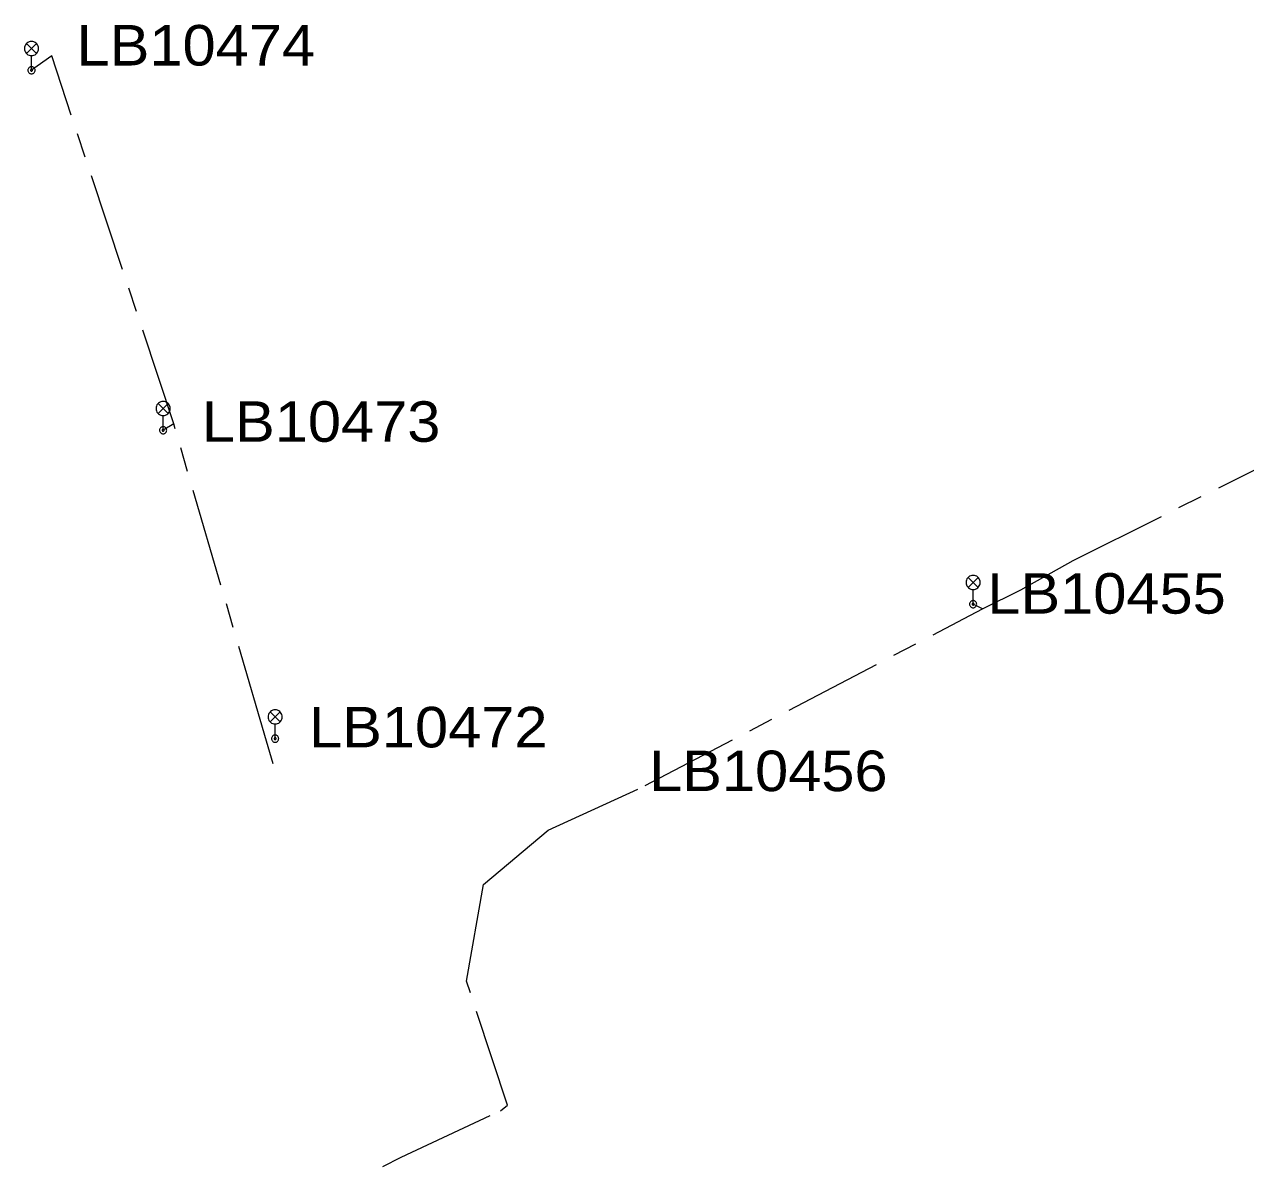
# Model space of a CAD drawing. Extents: x -691843 to -691118, y -976392 to -975793.
# Drawn here: x -691843.2 to -691778.5, y -976381.8 to -976321.3 of the extents above; entities that cross this region are included whole.
import ezdxf

# ---------------------------------------------------------------- set-up
doc = ezdxf.new("R2010")
doc.units = 0
doc.header["$LTSCALE"] = 0.87
doc.linetypes.add('LONG_DASH_SHORT_DASH', pattern=[9.9, 6, -1.2, 1.5, -1.2])
doc.layers.add('1', color=7, linetype='Continuous', lineweight=13)

msp = doc.modelspace()

# ---------------------------------------------------------------- linework, layer by layer
at = {"layer": '1'}
for p, q in [((-691843.095, -976322.285), (-691842.565, -976322.815)), ((-691843.095, -976322.815), (-691842.565, -976322.285)), ((-691842.83, -976323.7), (-691842.83, -976322.925)), ((-691836.125, -976341.345), (-691835.595, -976341.875)), ((-691836.125, -976341.875), (-691835.595, -976341.345)), ((-691835.86, -976342.76), (-691835.86, -976341.985)), ((-691793.235, -976350.555), (-691792.705, -976351.085)), ((-691793.235, -976351.085), (-691792.705, -976350.555)), ((-691792.97, -976351.97), (-691792.97, -976351.195)), ((-691830.195, -976357.675), (-691829.665, -976358.205)), ((-691830.195, -976358.205), (-691829.665, -976357.675)), ((-691829.93, -976359.09), (-691829.93, -976358.315))]:
    msp.add_line(p, q, dxfattribs=at)
at = {"layer": '1', "linetype": 'LONG_DASH_SHORT_DASH'}
for p, q in [((-691841.76, -976322.94), (-691842.83, -976323.7)), ((-691841.76, -976322.94), (-691842.83, -976323.7)), ((-691841.76, -976322.94), (-691842.83, -976323.7)), ((-691841.76, -976322.94), (-691842.83, -976323.7)), ((-691841.76, -976322.94), (-691842.83, -976323.7)), ((-691841.76, -976322.94), (-691842.83, -976323.7)), ((-691841.76, -976322.94), (-691842.83, -976323.7)), ((-691841.76, -976322.94), (-691842.83, -976323.7)), ((-691835.3, -976342.42), (-691835.86, -976342.76)), ((-691835.3, -976342.42), (-691835.86, -976342.76)), ((-691835.3, -976342.42), (-691835.86, -976342.76)), ((-691835.3, -976342.42), (-691835.86, -976342.76)), ((-691835.3, -976342.42), (-691835.86, -976342.76)), ((-691835.3, -976342.42), (-691835.86, -976342.76)), ((-691835.3, -976342.42), (-691835.86, -976342.76)), ((-691835.3, -976342.42), (-691835.86, -976342.76)), ((-691790.45, -976351.22), (-691787.67, -976349.66)), ((-691790.45, -976351.22), (-691787.67, -976349.66)), ((-691790.45, -976351.22), (-691787.67, -976349.66)), ((-691790.45, -976351.22), (-691787.67, -976349.66)), ((-691790.45, -976351.22), (-691787.67, -976349.66)), ((-691790.45, -976351.22), (-691787.67, -976349.66)), ((-691790.45, -976351.22), (-691787.67, -976349.66)), ((-691792.47, -976352.22), (-691792.97, -976351.97)), ((-691792.47, -976352.22), (-691792.97, -976351.97)), ((-691792.47, -976352.22), (-691792.97, -976351.97)), ((-691792.47, -976352.22), (-691792.97, -976351.97)), ((-691792.47, -976352.22), (-691792.97, -976351.97)), ((-691792.47, -976352.22), (-691792.97, -976351.97)), ((-691792.47, -976352.22), (-691792.97, -976351.97)), ((-691792.47, -976352.22), (-691792.97, -976351.97))]:
    msp.add_line(p, q, dxfattribs=at)
at = {"layer": '1'}
for points in [[(-691842.455, -976322.55), (-691842.461, -976322.485), (-691842.478, -976322.422), (-691842.505, -976322.362), (-691842.543, -976322.309), (-691842.589, -976322.263), (-691842.642, -976322.225), (-691842.702, -976322.198), (-691842.765, -976322.181), (-691842.83, -976322.175), (-691842.895, -976322.181), (-691842.958, -976322.198), (-691843.018, -976322.225), (-691843.071, -976322.263), (-691843.117, -976322.309), (-691843.155, -976322.362), (-691843.182, -976322.422), (-691843.199, -976322.485), (-691843.205, -976322.55), (-691843.199, -976322.615), (-691843.182, -976322.678), (-691843.155, -976322.737), (-691843.117, -976322.791), (-691843.071, -976322.837), (-691843.018, -976322.875), (-691842.958, -976322.902), (-691842.895, -976322.919), (-691842.83, -976322.925), (-691842.765, -976322.919), (-691842.702, -976322.902), (-691842.642, -976322.875), (-691842.589, -976322.837), (-691842.543, -976322.791), (-691842.505, -976322.737), (-691842.478, -976322.678), (-691842.461, -976322.615)], [(-691842.64, -976323.7), (-691842.643, -976323.667), (-691842.651, -976323.635), (-691842.665, -976323.605), (-691842.684, -976323.578), (-691842.708, -976323.554), (-691842.735, -976323.535), (-691842.765, -976323.521), (-691842.797, -976323.513), (-691842.83, -976323.51), (-691842.863, -976323.513), (-691842.895, -976323.521), (-691842.925, -976323.535), (-691842.952, -976323.554), (-691842.976, -976323.578), (-691842.995, -976323.605), (-691843.009, -976323.635), (-691843.017, -976323.667), (-691843.02, -976323.7), (-691843.017, -976323.733), (-691843.009, -976323.765), (-691842.995, -976323.795), (-691842.976, -976323.822), (-691842.952, -976323.846), (-691842.925, -976323.865), (-691842.895, -976323.879), (-691842.863, -976323.887), (-691842.83, -976323.89), (-691842.797, -976323.887), (-691842.765, -976323.879), (-691842.735, -976323.865), (-691842.708, -976323.846), (-691842.684, -976323.822), (-691842.665, -976323.795), (-691842.651, -976323.765), (-691842.643, -976323.733)], [(-691842.78, -976323.7), (-691842.781, -976323.691), (-691842.783, -976323.683), (-691842.787, -976323.675), (-691842.792, -976323.668), (-691842.798, -976323.662), (-691842.805, -976323.657), (-691842.813, -976323.653), (-691842.821, -976323.651), (-691842.83, -976323.65), (-691842.839, -976323.651), (-691842.847, -976323.653), (-691842.855, -976323.657), (-691842.862, -976323.662), (-691842.868, -976323.668), (-691842.873, -976323.675), (-691842.877, -976323.683), (-691842.879, -976323.691), (-691842.88, -976323.7), (-691842.879, -976323.709), (-691842.877, -976323.717), (-691842.873, -976323.725), (-691842.868, -976323.732), (-691842.862, -976323.738), (-691842.855, -976323.743), (-691842.847, -976323.747), (-691842.839, -976323.749), (-691842.83, -976323.75), (-691842.821, -976323.749), (-691842.813, -976323.747), (-691842.805, -976323.743), (-691842.798, -976323.738), (-691842.792, -976323.732), (-691842.787, -976323.725), (-691842.783, -976323.717), (-691842.781, -976323.709)], [(-691835.485, -976341.61), (-691835.491, -976341.545), (-691835.508, -976341.482), (-691835.535, -976341.423), (-691835.573, -976341.369), (-691835.619, -976341.323), (-691835.672, -976341.285), (-691835.732, -976341.258), (-691835.795, -976341.241), (-691835.86, -976341.235), (-691835.925, -976341.241), (-691835.988, -976341.258), (-691836.048, -976341.285), (-691836.101, -976341.323), (-691836.147, -976341.369), (-691836.185, -976341.423), (-691836.212, -976341.482), (-691836.229, -976341.545), (-691836.235, -976341.61), (-691836.229, -976341.675), (-691836.212, -976341.738), (-691836.185, -976341.798), (-691836.147, -976341.851), (-691836.101, -976341.897), (-691836.048, -976341.935), (-691835.988, -976341.962), (-691835.925, -976341.979), (-691835.86, -976341.985), (-691835.795, -976341.979), (-691835.732, -976341.962), (-691835.672, -976341.935), (-691835.619, -976341.897), (-691835.573, -976341.851), (-691835.535, -976341.798), (-691835.508, -976341.738), (-691835.491, -976341.675)], [(-691835.67, -976342.76), (-691835.673, -976342.727), (-691835.681, -976342.695), (-691835.695, -976342.665), (-691835.714, -976342.638), (-691835.738, -976342.614), (-691835.765, -976342.595), (-691835.795, -976342.581), (-691835.827, -976342.573), (-691835.86, -976342.57), (-691835.893, -976342.573), (-691835.925, -976342.581), (-691835.955, -976342.595), (-691835.982, -976342.614), (-691836.006, -976342.638), (-691836.025, -976342.665), (-691836.039, -976342.695), (-691836.047, -976342.727), (-691836.05, -976342.76), (-691836.047, -976342.793), (-691836.039, -976342.825), (-691836.025, -976342.855), (-691836.006, -976342.882), (-691835.982, -976342.906), (-691835.955, -976342.925), (-691835.925, -976342.939), (-691835.893, -976342.947), (-691835.86, -976342.95), (-691835.827, -976342.947), (-691835.795, -976342.939), (-691835.765, -976342.925), (-691835.738, -976342.906), (-691835.714, -976342.882), (-691835.695, -976342.855), (-691835.681, -976342.825), (-691835.673, -976342.793)], [(-691835.81, -976342.76), (-691835.811, -976342.751), (-691835.813, -976342.743), (-691835.817, -976342.735), (-691835.822, -976342.728), (-691835.828, -976342.722), (-691835.835, -976342.717), (-691835.843, -976342.713), (-691835.851, -976342.711), (-691835.86, -976342.71), (-691835.869, -976342.711), (-691835.877, -976342.713), (-691835.885, -976342.717), (-691835.892, -976342.722), (-691835.898, -976342.728), (-691835.903, -976342.735), (-691835.907, -976342.743), (-691835.909, -976342.751), (-691835.91, -976342.76), (-691835.909, -976342.769), (-691835.907, -976342.777), (-691835.903, -976342.785), (-691835.898, -976342.792), (-691835.892, -976342.798), (-691835.885, -976342.803), (-691835.877, -976342.807), (-691835.869, -976342.809), (-691835.86, -976342.81), (-691835.851, -976342.809), (-691835.843, -976342.807), (-691835.835, -976342.803), (-691835.828, -976342.798), (-691835.822, -976342.792), (-691835.817, -976342.785), (-691835.813, -976342.777), (-691835.811, -976342.769)], [(-691792.595, -976350.82), (-691792.601, -976350.755), (-691792.618, -976350.692), (-691792.645, -976350.633), (-691792.683, -976350.579), (-691792.729, -976350.533), (-691792.782, -976350.495), (-691792.842, -976350.468), (-691792.905, -976350.451), (-691792.97, -976350.445), (-691793.035, -976350.451), (-691793.098, -976350.468), (-691793.158, -976350.495), (-691793.211, -976350.533), (-691793.257, -976350.579), (-691793.295, -976350.633), (-691793.322, -976350.692), (-691793.339, -976350.755), (-691793.345, -976350.82), (-691793.339, -976350.885), (-691793.322, -976350.948), (-691793.295, -976351.008), (-691793.257, -976351.061), (-691793.211, -976351.107), (-691793.158, -976351.145), (-691793.098, -976351.172), (-691793.035, -976351.189), (-691792.97, -976351.195), (-691792.905, -976351.189), (-691792.842, -976351.172), (-691792.782, -976351.145), (-691792.729, -976351.107), (-691792.683, -976351.061), (-691792.645, -976351.008), (-691792.618, -976350.948), (-691792.601, -976350.885)], [(-691792.78, -976351.97), (-691792.783, -976351.937), (-691792.791, -976351.905), (-691792.805, -976351.875), (-691792.824, -976351.848), (-691792.848, -976351.824), (-691792.875, -976351.805), (-691792.905, -976351.791), (-691792.937, -976351.783), (-691792.97, -976351.78), (-691793.003, -976351.783), (-691793.035, -976351.791), (-691793.065, -976351.805), (-691793.092, -976351.824), (-691793.116, -976351.848), (-691793.135, -976351.875), (-691793.149, -976351.905), (-691793.157, -976351.937), (-691793.16, -976351.97), (-691793.157, -976352.003), (-691793.149, -976352.035), (-691793.135, -976352.065), (-691793.116, -976352.092), (-691793.092, -976352.116), (-691793.065, -976352.135), (-691793.035, -976352.149), (-691793.003, -976352.157), (-691792.97, -976352.16), (-691792.937, -976352.157), (-691792.905, -976352.149), (-691792.875, -976352.135), (-691792.848, -976352.116), (-691792.824, -976352.092), (-691792.805, -976352.065), (-691792.791, -976352.035), (-691792.783, -976352.003)], [(-691792.92, -976351.97), (-691792.921, -976351.961), (-691792.923, -976351.953), (-691792.927, -976351.945), (-691792.932, -976351.938), (-691792.938, -976351.932), (-691792.945, -976351.927), (-691792.953, -976351.923), (-691792.961, -976351.921), (-691792.97, -976351.92), (-691792.979, -976351.921), (-691792.987, -976351.923), (-691792.995, -976351.927), (-691793.002, -976351.932), (-691793.008, -976351.938), (-691793.013, -976351.945), (-691793.017, -976351.953), (-691793.019, -976351.961), (-691793.02, -976351.97), (-691793.019, -976351.979), (-691793.017, -976351.987), (-691793.013, -976351.995), (-691793.008, -976352.002), (-691793.002, -976352.008), (-691792.995, -976352.013), (-691792.987, -976352.017), (-691792.979, -976352.019), (-691792.97, -976352.02), (-691792.961, -976352.019), (-691792.953, -976352.017), (-691792.945, -976352.013), (-691792.938, -976352.008), (-691792.932, -976352.002), (-691792.927, -976351.995), (-691792.923, -976351.987), (-691792.921, -976351.979)], [(-691829.555, -976357.94), (-691829.561, -976357.875), (-691829.578, -976357.812), (-691829.605, -976357.753), (-691829.643, -976357.699), (-691829.689, -976357.653), (-691829.742, -976357.615), (-691829.802, -976357.588), (-691829.865, -976357.571), (-691829.93, -976357.565), (-691829.995, -976357.571), (-691830.058, -976357.588), (-691830.118, -976357.615), (-691830.171, -976357.653), (-691830.217, -976357.699), (-691830.255, -976357.753), (-691830.282, -976357.812), (-691830.299, -976357.875), (-691830.305, -976357.94), (-691830.299, -976358.005), (-691830.282, -976358.068), (-691830.255, -976358.128), (-691830.217, -976358.181), (-691830.171, -976358.227), (-691830.118, -976358.265), (-691830.058, -976358.292), (-691829.995, -976358.309), (-691829.93, -976358.315), (-691829.865, -976358.309), (-691829.802, -976358.292), (-691829.742, -976358.265), (-691829.689, -976358.227), (-691829.643, -976358.181), (-691829.605, -976358.128), (-691829.578, -976358.068), (-691829.561, -976358.005)], [(-691829.74, -976359.09), (-691829.743, -976359.057), (-691829.751, -976359.025), (-691829.765, -976358.995), (-691829.784, -976358.968), (-691829.808, -976358.944), (-691829.835, -976358.925), (-691829.865, -976358.911), (-691829.897, -976358.903), (-691829.93, -976358.9), (-691829.963, -976358.903), (-691829.995, -976358.911), (-691830.025, -976358.925), (-691830.052, -976358.944), (-691830.076, -976358.968), (-691830.095, -976358.995), (-691830.109, -976359.025), (-691830.117, -976359.057), (-691830.12, -976359.09), (-691830.117, -976359.123), (-691830.109, -976359.155), (-691830.095, -976359.185), (-691830.076, -976359.212), (-691830.052, -976359.236), (-691830.025, -976359.255), (-691829.995, -976359.269), (-691829.963, -976359.277), (-691829.93, -976359.28), (-691829.897, -976359.277), (-691829.865, -976359.269), (-691829.835, -976359.255), (-691829.808, -976359.236), (-691829.784, -976359.212), (-691829.765, -976359.185), (-691829.751, -976359.155), (-691829.743, -976359.123)], [(-691829.88, -976359.09), (-691829.881, -976359.081), (-691829.883, -976359.073), (-691829.887, -976359.065), (-691829.892, -976359.058), (-691829.898, -976359.052), (-691829.905, -976359.047), (-691829.913, -976359.043), (-691829.921, -976359.041), (-691829.93, -976359.04), (-691829.939, -976359.041), (-691829.947, -976359.043), (-691829.955, -976359.047), (-691829.962, -976359.052), (-691829.968, -976359.058), (-691829.973, -976359.065), (-691829.977, -976359.073), (-691829.979, -976359.081), (-691829.98, -976359.09), (-691829.979, -976359.099), (-691829.977, -976359.107), (-691829.973, -976359.115), (-691829.968, -976359.122), (-691829.962, -976359.128), (-691829.955, -976359.133), (-691829.947, -976359.137), (-691829.939, -976359.139), (-691829.93, -976359.14), (-691829.921, -976359.139), (-691829.913, -976359.137), (-691829.905, -976359.133), (-691829.898, -976359.128), (-691829.892, -976359.122), (-691829.887, -976359.115), (-691829.883, -976359.107), (-691829.881, -976359.099)]]:
    msp.add_lwpolyline(points, close=True, dxfattribs=at)
at = {"layer": '1', "linetype": 'LONG_DASH_SHORT_DASH'}
for points in [[(-691830.04, -976360.42), (-691830.389, -976359.224), (-691835.3, -976342.42), (-691841.76, -976322.94)], [(-691830.04, -976360.42), (-691830.389, -976359.224), (-691835.3, -976342.42), (-691841.76, -976322.94)], [(-691830.04, -976360.42), (-691830.389, -976359.224), (-691835.3, -976342.42), (-691841.76, -976322.94)], [(-691830.04, -976360.42), (-691830.389, -976359.224), (-691835.3, -976342.42), (-691841.76, -976322.94)], [(-691830.04, -976360.42), (-691830.389, -976359.224), (-691835.3, -976342.42), (-691841.76, -976322.94)], [(-691830.04, -976360.42), (-691830.389, -976359.224), (-691835.3, -976342.42), (-691841.76, -976322.94)], [(-691830.04, -976360.42), (-691830.389, -976359.224), (-691835.3, -976342.42), (-691841.76, -976322.94)], [(-691830.04, -976360.42), (-691830.389, -976359.224), (-691835.3, -976342.42), (-691841.76, -976322.94)], [(-691787.67, -976349.66), (-691775.06, -976343.35), (-691767.16, -976339.65), (-691763.13, -976338.25), (-691757.43, -976337.91)], [(-691787.67, -976349.66), (-691775.06, -976343.35), (-691767.16, -976339.65), (-691763.13, -976338.25), (-691757.43, -976337.91)], [(-691787.67, -976349.66), (-691775.06, -976343.35), (-691767.16, -976339.65), (-691763.13, -976338.25), (-691757.43, -976337.91)], [(-691787.67, -976349.66), (-691775.06, -976343.35), (-691767.16, -976339.65), (-691763.13, -976338.25), (-691757.43, -976337.91)], [(-691787.67, -976349.66), (-691775.06, -976343.35), (-691767.16, -976339.65), (-691763.13, -976338.25), (-691757.43, -976337.91)], [(-691787.67, -976349.66), (-691775.06, -976343.35), (-691767.16, -976339.65), (-691763.13, -976338.25), (-691757.43, -976337.91)], [(-691787.67, -976349.66), (-691775.06, -976343.35), (-691767.16, -976339.65), (-691763.13, -976338.25), (-691757.43, -976337.91)], [(-691787.67, -976349.66), (-691775.06, -976343.35), (-691767.16, -976339.65), (-691763.13, -976338.25), (-691757.43, -976337.91)], [(-691824.22, -976381.75), (-691823.26, -976381.26), (-691818, -976378.79), (-691817.62, -976378.5), (-691819.8, -976371.93), (-691818.89, -976366.82), (-691815.47, -976363.94), (-691810.34, -976361.58), (-691792.47, -976352.22), (-691790.45, -976351.22), (-691787.67, -976349.66)], [(-691824.22, -976381.75), (-691823.26, -976381.26), (-691818, -976378.79), (-691817.62, -976378.5), (-691819.8, -976371.93), (-691818.89, -976366.82), (-691815.47, -976363.94), (-691810.34, -976361.58), (-691792.47, -976352.22), (-691790.45, -976351.22)], [(-691824.22, -976381.75), (-691823.26, -976381.26), (-691818, -976378.79), (-691817.62, -976378.5), (-691819.8, -976371.93), (-691818.89, -976366.82), (-691815.47, -976363.94), (-691810.34, -976361.58), (-691792.47, -976352.22), (-691790.45, -976351.22)], [(-691824.22, -976381.75), (-691823.26, -976381.26), (-691818, -976378.79), (-691817.62, -976378.5), (-691819.8, -976371.93), (-691818.89, -976366.82), (-691815.47, -976363.94), (-691810.34, -976361.58), (-691792.47, -976352.22), (-691790.45, -976351.22)], [(-691824.22, -976381.75), (-691823.26, -976381.26), (-691818, -976378.79), (-691817.62, -976378.5), (-691819.8, -976371.93), (-691818.89, -976366.82), (-691815.47, -976363.94), (-691810.34, -976361.58), (-691792.47, -976352.22), (-691790.45, -976351.22)], [(-691824.22, -976381.75), (-691823.26, -976381.26), (-691818, -976378.79), (-691817.62, -976378.5), (-691819.8, -976371.93), (-691818.89, -976366.82), (-691815.47, -976363.94), (-691810.34, -976361.58), (-691792.47, -976352.22), (-691790.45, -976351.22)], [(-691824.22, -976381.75), (-691823.26, -976381.26), (-691818, -976378.79), (-691817.62, -976378.5), (-691819.8, -976371.93), (-691818.89, -976366.82), (-691815.47, -976363.94), (-691810.34, -976361.58), (-691792.47, -976352.22), (-691790.45, -976351.22)], [(-691824.22, -976381.75), (-691823.26, -976381.26), (-691818, -976378.79), (-691817.62, -976378.5), (-691819.8, -976371.93), (-691818.89, -976366.82), (-691815.47, -976363.94), (-691810.34, -976361.58), (-691792.47, -976352.22), (-691790.45, -976351.22)]]:
    msp.add_lwpolyline(points, dxfattribs=at)

# ---------------------------------------------------------------- texts
at = {"layer": '1', "width": 1.1}
for s, p in [('LB10474', (-691840.444, -976323.449)), ('LB10473', (-691833.806, -976343.373)), ('LB10455', (-691792.218, -976352.473)), ('LB10472', (-691828.134, -976359.553)), ('LB10456', (-691810.127, -976361.87))]:
    msp.add_text(s, height=2.144, dxfattribs=at).set_placement(p)

doc.saveas('drawing.dxf')
